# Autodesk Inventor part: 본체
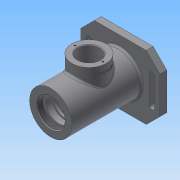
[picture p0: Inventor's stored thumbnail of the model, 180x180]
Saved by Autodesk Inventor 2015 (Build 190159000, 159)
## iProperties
Created: 2017-10
Part Number: 본체
Material: 일반
Document SubType Name: Modeling
Designer: Administrator
Density: 1 g/cm^3
Appearance: 기본값
Author: Administrator
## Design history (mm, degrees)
sketch "스케치1"
  geometry: C1 r 31 at (0, 0); 1 further point
  constraints: 1 centre point, 1 coincident
  dimensions: "d0" = 62 diameter of C1
extrude "돌출1" new body sketch "스케치1" stored distance "d1" = 115; taper "d2" = 0 deg
sketch "스케치2"
  geometry: L1 (47, 58)-(-47, 58); L2 (-47, 58)-(-47, -58); L3 (-47, -58)-(47, -58); L4 (47, -58)-(47, 58); 3 further points
  constraints: 8 end point, 2 midpoint, 2 parallel, 1 horizontal, 1 horizontal alignment, 1 perpendicular, 1 vertical alignment
  dimensions: "d3" = 94 distance between parallel lines of L2 L4; "d4" = 116 distance between parallel lines of L3 L1
extrude "돌출2" join sketch "스케치2" distance "d5" = 13; taper "d6" = 0 deg
sketch "스케치3"
  geometry: L1 (47, 58)-(-47, 58) reference; L2 (-47, 58)-(-47, -58) reference; L3 (-47, -58)-(47, -58) reference; L4 (47, -58)-(47, 58) reference; C1 r 35 at (0, 0); 1 further point
  constraints: 1 centre point, 1 coincident
  dimensions: "d7" = 70 diameter of C1
extrude "돌출3" cut sketch "스케치3" distance "d8" = 3; taper "d9" = 0 deg
node "작업 평면1"
sketch "스케치4"
  geometry: L1 (31, 57.5)-(-31, 57.5) reference; C1 r 25 at (0, 1.5); 1 further point
  constraints: 1 centre point, 1 vertical alignment
  dimensions: "d11" = 50 diameter of C1; "d12" = 56 distance from line of C1.centre L1
extrude "돌출4" join sketch "스케치4" stored distance "d13" = 3; taper "d14" = 0 deg
sketch "스케치5"
  geometry: L1 (-35, -57.5)-(35, -57.5) reference; L2 (22, -57.5)-(16, -43.5); L3 (16, -43.5)-(12.5, -43.5); L4 (12.5, -43.5)-(12.5, -36.2); L5 (12.5, -36.2)-(10, -36.2); L6 (10, -36.2)-(10, -33.5); L7 (10, -33.5)-(0, -33.5); L8 (0, -33.5)-(0, -57.5); 1 further point
  constraints: 14 end point, 3 perpendicular, 1 midpoint, 1 parallel, 1 point on line, 1 vertical
  dimensions: "d16" = 24 distance of L7.end L8.end; "d18" = 32 diameter of L2.end L8; "d19" = 14 vertical distance of L2.start L2.end; "d20" = 2.7 distance from line of L5.end L7; "d21" = 20 diameter of L6 L8; "d22" = 44 diameter of L2.start L8; "d23" = 25 diameter of L4 L8; "d24" = 7.3 distance of L3.end L4.end (derived)
revolve "회전1" sketch "스케치5" stored, may be unused: angle "d25" = 90 deg
sketch "스케치6"
  geometry: 2 further points
  constraints: 1 coincident
hole "구멍1" sketch "스케치6" at (0, 0) diameter "d26" = 40.376; stored, may be unused: countersink angle "d30" = 90 deg, drill point angle "d32" = 0 deg; dims "d27" = 84, "d28" = 4, "d29" = 2, "d31" = 9
sketch "스케치7"
  geometry: L1 (24, 48.5)-(24, 45.5); L2 (24, 45.5)-(20, 45.5); L3 (20, 45.5)-(20, 36.5); L4 (20, 36.5)-(17.5, 36.5); L5 (17.5, 36.5)-(17.5, 33.25); L6 (17.5, 33.25)-(18.5, 33.25); L7 (18.5, 33.25)-(18.5, 31.5); L8 (18.5, 31.5)-(17.5, 31.5); L9 (17.5, 31.5)-(17.5, 20.5); L10 (17.5, 20.5)-(26, 20.5); L11 (26, 20.5)-(26, -17.5); L12 (26, -17.5)-(17.5, -17.5); L13 (17.5, -17.5)-(17.5, -28.5); L14 (17.5, -28.5)-(16.5, -28.5); L15 (16.5, -28.5)-(16.5, -33.5); L16 (0, 48.5)-(0, -33.5); L17 (24, 48.5)-(0, 48.5); L18 (20.188, 48.5)-(-20.188, 48.5) reference; L19 (16.5, -33.5)-(0, -33.5); L20 (10, -33.5)-(-10, -33.5) reference; L21 (-20.188, 57.5)-(20.188, 57.5) reference; 2 further points
  constraints: 36 end point, 13 perpendicular, 3 midpoint, 2 point on line, 1 collinear, 1 horizontal, 1 vertical alignment
  dimensions: "d33" = 48 diameter of L1 L16; "d34" = 82 distance of L16.end L16.start; "d35" = 3 distance of L1.start L1.end; "d36" = 40 diameter of L3 L16; "d37" = 35 diameter of L5 L16; "d39" = 52 diameter of L11 L16; "d40" = 35 diameter of L13 L16; "d41" = 33 diameter of L15 L16; "d42" = 5 distance from line of L19 L13.end; "d43" = 11 distance from line of L14 L11.end; "d44" = 38 distance of L10.end L11.end; "d47" = 21 distance from line of L21 L3.end; "d48" = 1.75 distance of L6.end L7.end; "d49" = 26 distance from line of L21 L7.end; "d50" = 11 distance of L9.end L8.end (derived); "d51" = 37 diameter of L7 L16
revolve "회전2" sketch "스케치7" stored, may be unused: angle "d52" = 90 deg
fillet "모깎기1" dims "d53" = 0.3
fillet "모깎기2" dims "d54" = 3
fillet "모깎기3" dims "d55" = 3
fillet "모깎기4" dims "d56" = 3
chamfer "모따기1" distance "d57" = 1; stored, may be unused: second distance "d58" = 2, angle "d59" = 45 deg
fillet "모깎기5" dims "d60" = 0.3
chamfer "모따기2" distance "d61" = 0.7; stored, may be unused: second distance "d62" = 2, angle "d63" = 30 deg
chamfer "모따기3" distance "d64" = 20; stored, may be unused: second distance "d65" = 2, angle "d66" = 30 deg
sketch "스케치8"
  geometry: 1 further point
sketch "스케치9"
  geometry: L1 (-20, 50)-(20, 50); L2 (20, 42)-(-20, 42); A1 r 4 centre (20, 46) between (20, 42) and (20, 50); A2 r 4 centre (-20, 46) between (-20, 50) and (-20, 42); 2 further points
  constraints: 4 end point, 4 point on circle, 4 tangent, 2 centre point, 1 horizontal, 1 midpoint, 1 parallel, 1 vertical alignment
  dimensions: "d67" = 40 distance of A2.centre A1.centre; "d68" = 4 radius of A1; "d69" = 46 vertical distance of point (0, 0) A2.centre
extrude "돌출5" cut sketch "스케치9" stored distance "d70" = 3; taper "d71" = 0 deg
fillet "모깎기6" dims "d72" = 3
node "작업 평면2"
sketch "스케치10"
  geometry: L1 (-16, 56)-(-78, 56) reference; L2 (0, -25)-(0, 25) reference; 3 further points
  constraints: 1 coincident, 1 other
  dimensions: "d73" = 56 distance from line of point (-10, 0) L1; "d74" = 10 distance from line of point (-10, 0) L2
feature "엠보싱1" sketch "스케치10" dims "d9" = 0, "d75" = 0.5, "d76" = 0
sketch "스케치11"
  geometry: C1 r 25 at (0, 0) reference; C2 r 16 at (0, 0); 1 further point
  constraints: 1 centre point, 1 coincident
  dimensions: "d78" = 32 diameter of C2
extrude "돌출6" cut sketch "스케치11" stored distance "d79" = 3; taper "d80" = 0 deg
sketch "스케치12" dims "d81" = 41
  geometry: C1 r 25 at (0, 0) reference; 3 further points
  constraints: 2 vertical alignment, 1 coincident, 2 other
hole "구멍2" sketch "스케치12" at (0, -20.5) diameter "d82" = 2.459; stored, may be unused: countersink angle "d86" = 90 deg, drill point angle "d88" = 120 deg; dims "d83" = 6, "d84" = 4, "d85" = 2, "d87" = 8
fillet "모깎기7" dims "d92" = 3
chamfer "모따기4" distance "d93" = 1; stored, may be unused: second distance "d94" = 2, angle "d95" = 30 deg
node "솔리드1"
mirror "대칭1"
pattern_circular "원형 패턴1" dims angle "d90" = 360 deg
node "투영된 루프1"
other parameters: "d10" = -47
